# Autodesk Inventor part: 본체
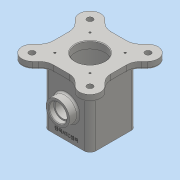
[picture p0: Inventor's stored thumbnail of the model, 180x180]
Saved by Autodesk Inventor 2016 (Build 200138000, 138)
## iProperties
Created: 2019-11
Part Number: 본체
Material: 일반
Document SubType Name: Modeling
Designer: user
Density: 1 g/cm^3
Appearance: 기본값
Author: user
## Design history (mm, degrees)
sketch "스케치1"
  geometry: L1 (49, -49)-(-49, -49); L2 (-49, -49)-(-49, 49); L3 (-49, 49)-(49, 49); L4 (49, 49)-(49, -49); L5 (49, -49)-(-49, 49); L6 (-49, -49)-(49, 49); L7 (-49, -49)-(49, 49); L8 (-61.728, -36.272)-(36.272, 61.728); L9 (61.728, 36.272)-(-36.272, -61.728); L10 (-49, 49)-(49, -49); L11 (-36.272, 61.728)-(61.728, -36.272); L12 (36.272, -61.728)-(-61.728, 36.272); A1 r 18 centre (-49, -49) between (-61.728, -36.272) and (-36.272, -61.728); A2 r 18 centre (49, 49) between (61.728, 36.272) and (36.272, 61.728); A3 r 18 centre (-49, 49) between (-36.272, 61.728) and (-61.728, 36.272); A4 r 18 centre (49, -49) between (36.272, -61.728) and (61.728, -36.272); 3 further points
  constraints: 28 end point, 8 point on circle, 8 tangent, 4 centre point, 4 midpoint, 4 parallel, 1 horizontal, 1 perpendicular
  dimensions: "d0" = 98 distance of L2.end L3.end; "d1" = 98 distance of L3.end L1.start; "d2" = 36 distance between parallel lines of L8 L9; "d3" = 36 distance between parallel lines of L12 L11
extrude "돌출1" new body sketch "스케치1" distance "d4" = 12; taper "d5" = 0 deg
sketch "스케치3" dims "d6" = 140
  geometry: L1 (-61.728, 36.272)-(-49, 23.544) reference; C1 r 9 at (-49.497, 49.497); 2 further points
  constraints: 1 centre point, 1 coincident, 3 other
  dimensions: "d7" = 18 diameter of C1; "d8" = 18 distance from line of C1.centre L1
hole "구멍1" sketch "스케치3" at (-49.497, 49.497) diameter "d9" = 10; stored, may be unused: countersink angle "d13" = 90 deg, drill point angle "d15" = 118 deg; dims "d10" = 6, "d11" = 18, "d12" = 4, "d14" = 8
sketch "스케치5"
  geometry: C1 r 25 at (0, 0); 1 further point
  constraints: 1 centre point, 1 coincident
  dimensions: "d25" = 50 diameter of C1
extrude "돌출2" cut sketch "스케치5" distance "d26" = 12; taper "d27" = 0 deg
sketch "스케치6"
  geometry: L1 (-30, -30)-(30, -30); L2 (30, -30)-(30, 30); L3 (30, 30)-(-30, 30); L4 (-30, 30)-(-30, -30); L5 (-30, -30)-(30, 30); L6 (30, -30)-(-30, 30); 2 further points
  constraints: 12 end point, 2 midpoint, 2 parallel, 1 coincident, 1 horizontal, 1 perpendicular
  dimensions: "d31" = 60 distance of L1.end L2.end; "d32" = 60 distance of L1.start L1.end
hole "구멍3" sketch "스케치6" at (30, 30) diameter "d33" = 3.242; stored, may be unused: countersink angle "d37" = 90 deg, drill point angle "d39" = 118 deg; dims "d34" = 8, "d35" = 18, "d36" = 5, "d38" = 10
sketch "스케치7"
  geometry: L1 (40, -40)-(-40, -40); L2 (-40, -40)-(-40, 40); L3 (-40, 40)-(40, 40); L4 (40, 40)-(40, -40); L5 (40, -40)-(-40, 40); L6 (-40, -40)-(40, 40); 1 further point
  constraints: 12 end point, 2 midpoint, 2 parallel, 1 horizontal, 1 perpendicular
  dimensions: "d43" = 80 distance of L1.start L1.end; "d44" = 80 distance of L1.end L2.end
extrude "돌출3" join sketch "스케치7" distance "d45" = 98; taper "d46" = 0 deg
sketch "스케치8"
  geometry: C1 r 25 at (0, 0); 1 further point
  constraints: 1 centre point, 1 coincident
  dimensions: "d47" = 50 diameter of C1
extrude "돌출4" cut sketch "스케치8" distance "d48" = 110; taper "d49" = 0 deg
sketch "스케치9"
  geometry: C1 r 35 at (0, 0); 1 further point
  constraints: 1 centre point, 1 coincident
  dimensions: "d50" = 70 diameter of C1
extrude "돌출5" cut sketch "스케치9" distance "d51" = 86; taper "d52" = 0 deg
node "작업 평면1"
sketch "스케치11"
  geometry: L1 (23.544, 0)-(36.272, 0) reference; C1 r 20 at (0, -49); 1 further point
  constraints: 1 centre point, 1 vertical alignment
  dimensions: "d54" = 40 diameter of C1; "d55" = 49 distance from line of L1 C1.centre
extrude "돌출6" join sketch "스케치11" stored distance "d56" = 86; taper "d57" = 0 deg
sketch "스케치12"
  geometry: C1 r 15 at (0, 0); 1 further point
  constraints: 1 centre point
  dimensions: "d58" = 30 diameter of C1
extrude "돌출7" cut sketch "스케치12" distance "d59" = 8; taper "d60" = 0 deg
sketch "스케치13"
  geometry: L1 (-23.544, 49)-(-36.272, 49) reference; C1 r 12.5 at (0, 0); 1 further point
  constraints: 1 centre point, 1 vertical alignment
  dimensions: "d61" = 25 diameter of C1; "d62" = 49 distance from line of L1 C1.centre
extrude "돌출8" cut sketch "스케치13" distance "d63" = 40; taper "d64" = 0 deg
sketch "스케치14"
  geometry: C1 r 1.621 at (30, -30) reference; 2 further points
  constraints: 1 coincident
hole "구멍4" sketch "스케치14" at (30, -30) diameter "d65" = 3.242; stored, may be unused: countersink angle "d69" = 90 deg, drill point angle "d71" = 118 deg; dims "d66" = 8, "d67" = 18, "d68" = 5, "d70" = 10
fillet "모깎기1" dims "d75" = 25
chamfer "모따기1" distance "d76" = 1; stored, may be unused: second distance "d77" = 2, angle "d78" = 45 deg
fillet "모깎기2" dims "d79" = 3
fillet "모깎기3" dims "d80" = 10
fillet "모깎기4" dims "d81" = 3
sketch "스케치15" dims "d0" = 98, "d1" = 98, "d2" = 36, "d3" = 36
  geometry: L1 (60, 0)-(0, 0) reference; C1 r 20 at (30, 49) reference; 2 further points
  constraints: 1 vertical alignment, 1 other
  dimensions: "d82" = 10 distance from line of L1 point (30, 10)
feature "엠보싱1" sketch "스케치15" dims "d0" = 98, "d1" = 98, "d2" = 36, "d3" = 36, "d83" = 0.5, "d84" = 0
fillet "모깎기5" dims "d85" = 3
node "솔리드1"
pattern_circular "원형 패턴1" dims angle "d29" = 360 deg
pattern_circular "원형 패턴2" dims angle "d41" = 360 deg
pattern_circular "원형 패턴3" dims angle "d73" = 360 deg
other parameters: "d53" = -55
